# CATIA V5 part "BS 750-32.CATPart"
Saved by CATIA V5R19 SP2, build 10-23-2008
Part number: BS 750-32
Bounding box of the stored display mesh (mm): x -22.494 to 22.494, y -22.494 to 22.494, z 0 to 96
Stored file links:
  C:\Users\Bora\Desktop\3D Katı model\BS serisi\BS 750\BS 750-32.CATPart
  C:\Program Files\Dassault Systemes\B19\intel_a\reffiles\standard\MetricThickPitch.txt
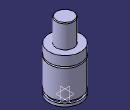
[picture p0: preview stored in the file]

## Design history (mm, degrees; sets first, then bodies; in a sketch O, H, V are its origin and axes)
Body1 (main body)
  Sketch1 on yz-plane, origin (0, 0, 0), H (0, 1, 0), V (0, 0, 1)
    point P3 (12.5, 95)
    point P5 (12.5, 95)
    point P7 (22.5, 49.5)
    point P8 (22.5, 47.5)
    point P12 (22.5, 47.5)
    point P13 (22.5, 49.5)
    line L1 (22.5, 0) -> (22.5, 4)
    line L2 (12.5, 95) -> (12.5, 63)
    arc A1 centre (11.5, 95) radius 1 from (12.5, 95) to (11.5, 96) ccw
    arc A2 centre (22.5, 48.5) radius 1 from (22.5, 49.5) to (22.5, 47.5) ccw
    line L3 (20, 7.5) -> (20, 4)
    line L4 (22.5, 7.5) -> (22.5, 47.5)
    line L5 (22.5, 49.5) -> (22.5, 63)
    line L6 (11.5, 96) -> (0, 96)
    point P15 (0, 96)
    line L7 (12.5, 63) -> (22.5, 63)
    line L8 (0, 0) -> (22.5, 0)
    line L9 (20, 7.5) -> (22.5, 7.5)
    line L10 (20, 4) -> (22.5, 4)
    coincidence: P15 V, P3 P5, P7 P13, P8 P12
    tangency: L6 A1
    horizontal: L7 H, L8 H, L9 H, L10 H
  Shaft1: profile Sketch1, axis Sketch1.V, angle 360
  Sketch2 on face of Shaft1 from Sketch1.L8, origin (0, 0, 0), H (1, 0, 0), V (0, -1, 0)
    point P1 (10, 0)
    distance P1 V = 10
  Hole1: placed by Sketch2, at (10, 0, 0) direction (0, 0, 1), diameter 6.647, depth 4, threaded "M8", thread diameter 8, thread depth 4, pitch 1.25
  CircPattern1: of Hole1, instances 2, angular step 180, axis from xy-plane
